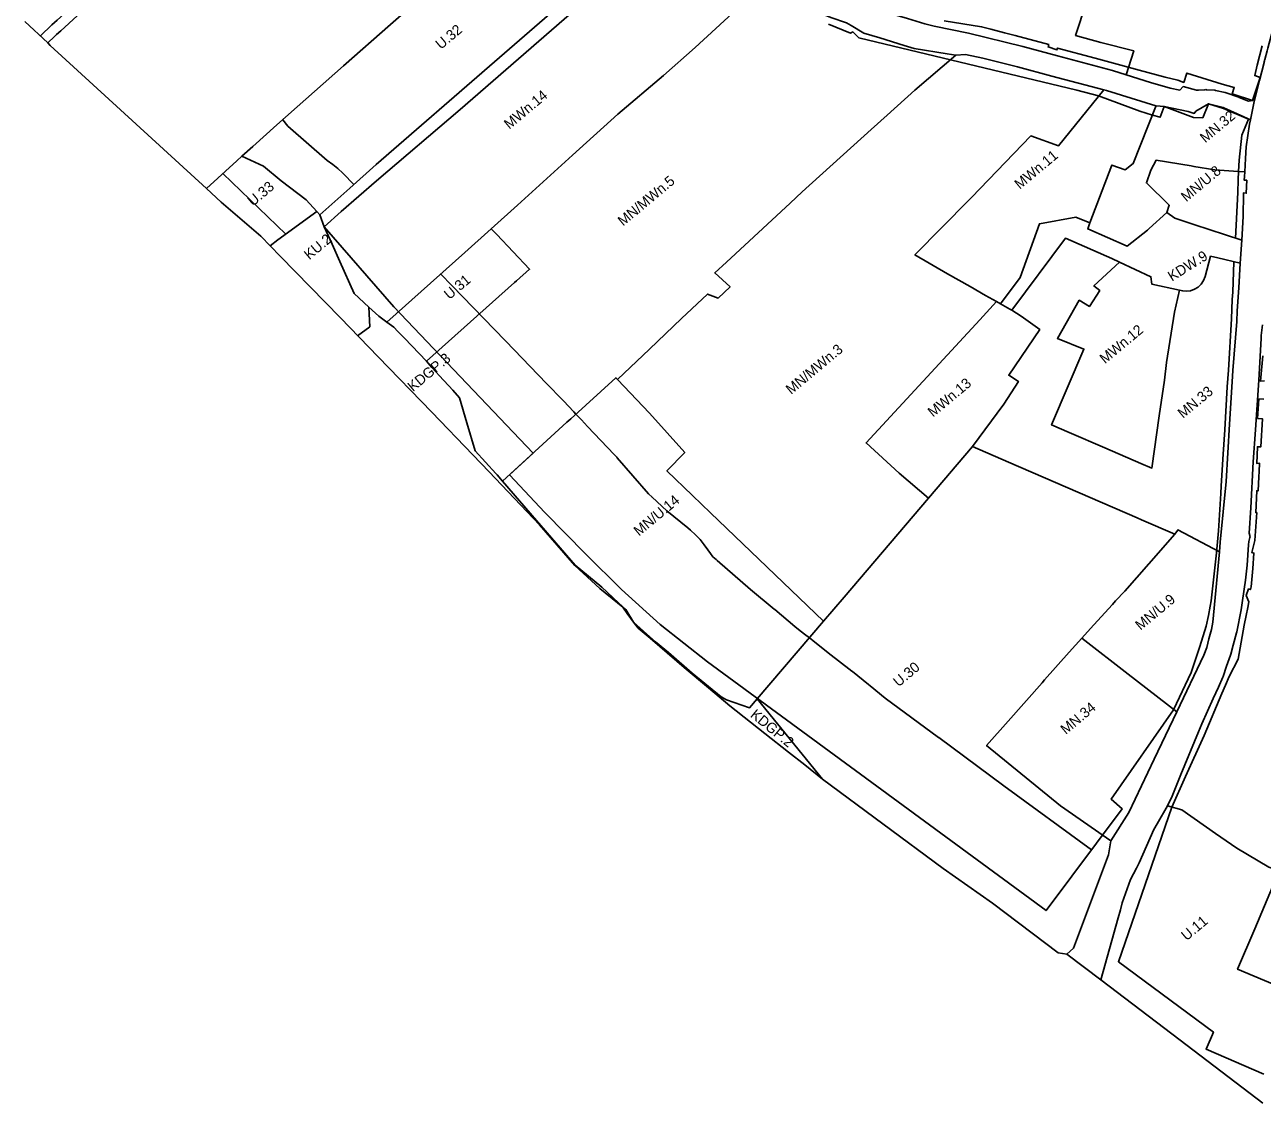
# Model space of a CAD drawing. Extents: x 7418616 to 7420822, y 5550745 to 5553106.
# Drawn here: x 7419438 to 7420041, y 5551094 to 5551619 of the extents above; entities that cross this region are included whole.
import ezdxf

# ---------------------------------------------------------------- set-up
doc = ezdxf.new("R2010")
doc.units = 0
for name, color, linetype in [('granica obszaru objętego planem', 7, 'Continuous'), ('granica strefy zwiększonej wysokości zabudowy', 7, 'Continuous'), ('linie rozgraniczające', 7, 'Continuous'), ('nieprzekraczalne linie zabudowy', 7, 'Continuous'), ('przeznaczenia terenów', 7, 'Continuous')]:
    doc.layers.add(name, color=color, linetype=linetype)

msp = doc.modelspace()

# ---------------------------------------------------------------- linework, layer by layer
at = {"layer": 'granica obszaru objętego planem'}
msp.add_lwpolyline([(7420041.04, 5551093.52), (7420000.75, 5551124.25), (7419962.19, 5551153.66), (7419945.54, 5551166.16), (7419941.34, 5551166.91), (7419909.33, 5551191.02), (7419885.31, 5551207.95), (7419826.5, 5551251.53), (7419817.94, 5551258.45), (7419810.05, 5551264.7), (7419798.45, 5551273.79), (7419781.42, 5551287.19), (7419771.03, 5551295.97), (7419759.16, 5551305.88), (7419742.57, 5551320.26), (7419736.76, 5551325.16), (7419734.5, 5551328.07), (7419731.34, 5551332.23), (7419729.3, 5551335.25), (7419718.06, 5551344.47), (7419705.9, 5551355.56), (7419688.74, 5551375.39), (7419664.22, 5551401.29), (7419656.17, 5551409.57), (7419636.17, 5551430.42), (7419610.04, 5551457.27), (7419591.7, 5551476.35), (7419562.41, 5551506.46), (7419552.94, 5551516.11), (7419533.63, 5551532.65), (7419526.39, 5551539.32), (7419450.23, 5551609.13), (7419449.2, 5551610.35), (7419437.9, 5551620.76)], dxfattribs=at)
at = {"layer": 'granica strefy zwiększonej wysokości zabudowy'}
for points in [[(7419563.59, 5551572.87), (7419566.06, 5551569.76), (7419585.29, 5551553.03), (7419587.95, 5551551.12), (7419590.48, 5551549.05), (7419592.86, 5551546.81), (7419593.2, 5551546.48), (7419598.1, 5551541.48), (7419598.26, 5551541.31)], [(7419640.56, 5551497.66), (7419645.97, 5551492.04), (7419672, 5551465.29), (7419672.25, 5551465.03), (7419692.14, 5551444.3), (7419700.07, 5551436.14), (7419700.49, 5551435.7), (7419705.3, 5551430.63), (7419705.35, 5551430.59), (7419706.43, 5551429.44)], [(7419706.34, 5551429.36), (7419709.16, 5551426.55), (7419712.11, 5551423.44), (7419725.06, 5551409.76), (7419726.33, 5551408.36), (7419726.55, 5551408.1), (7419741.75, 5551390.53), (7419743.54, 5551388.9), (7419743.56, 5551388.89), (7419750.79, 5551382.3), (7419761.01, 5551373.91), (7419762.27, 5551372.84), (7419764.66, 5551370.61), (7419766.89, 5551368.22), (7419768.97, 5551365.69), (7419770.73, 5551363.24), (7419771.93, 5551361.46), (7419773.14, 5551359.88), (7419774.81, 5551358.48), (7419775.32, 5551358.04), (7419791.56, 5551343.97), (7419803.07, 5551334.35), (7419803.3, 5551334.16), (7419813.04, 5551325.93), (7419814.94, 5551324.44), (7419817.87, 5551322.12), (7419820.16, 5551320.32)], [(7419820.16, 5551320.32), (7419821.84, 5551319), (7419829.32, 5551313.12), (7419840.89, 5551304.06), (7419841.1, 5551303.89), (7419848.99, 5551297.64), (7419849.76, 5551297.01), (7419857.1, 5551290.96), (7419883.07, 5551271.86), (7419883.22, 5551271.74), (7419914.97, 5551248.2), (7419957.62, 5551216.97)]]:
    msp.add_lwpolyline(points, dxfattribs=at)
at = {"layer": 'linie rozgraniczające'}
for p, q in [((7420030.8, 5551514.23), (7420030.08, 5551502.9)), ((7419913.29, 5551483.18), (7419911.35, 5551484.32)), ((7419899.62, 5551413.61), (7419878.15, 5551388.38)), ((7419827.08, 5551328.43), (7419794.8, 5551290.63)), ((7419794.8, 5551290.63), (7419826.5, 5551251.53))]:
    msp.add_line(p, q, dxfattribs=at)
for points in [[(7419449.2, 5551610.35), (7419452.46, 5551613.53), (7419453.31, 5551614.36), (7419455.41, 5551616.28), (7419477.43, 5551636.49), (7419488.09, 5551645.77), (7419515.75, 5551669.86), (7419570.49, 5551717.29), (7419589.38, 5551733.67), (7419610.42, 5551751.9), (7419613.77, 5551754.84), (7419627.2, 5551766.58)], [(7419537.25, 5551694.98), (7419524.25, 5551683.72), (7419519.48, 5551679.65), (7419513.7, 5551674.67), (7419507.7, 5551669.36), (7419503.04, 5551665.3), (7419495.61, 5551658.92), (7419488.4, 5551652.57), (7419483.64, 5551648.47), (7419474.37, 5551640.41), (7419458.68, 5551626.03), (7419453.73, 5551621.45), (7419451.05, 5551619.22), (7419445.5, 5551613.76)], [(7419700.4, 5551695.24), (7419687.42, 5551682.37), (7419674.24, 5551670.63), (7419662.03, 5551659.82), (7419633.04, 5551634.29), (7419616.09, 5551619.23), (7419593.15, 5551599.18), (7419560.75, 5551570.34), (7419548.95, 5551559.84), (7419543.61, 5551555.09)], [(7419974.49, 5551594.78), (7419976.92, 5551602.43), (7419978.21, 5551606.48), (7419962.1, 5551610.56), (7419949.9, 5551613.99), (7419954.99, 5551629.76), (7419950.26, 5551631.32), (7419949.77, 5551631.48), (7419940.41, 5551634.57), (7419942.5, 5551636.57), (7419948.98, 5551642.71), (7419959.79, 5551652.81), (7419962.71, 5551655.57), (7419975.98, 5551642.42), (7419989.51, 5551658.28), (7419990.82, 5551664.22), (7419994.68, 5551680.44)], [(7419753.76, 5551670.21), (7419765.49, 5551663.66), (7419774.08, 5551658.33), (7419781.54, 5551654.6), (7419788.27, 5551651.59), (7419797.81, 5551647.54), (7419808.59, 5551642.92), (7419818.54, 5551638.49), (7419827.18, 5551635.06), (7419834.06, 5551632.36), (7419844.69, 5551628.77), (7419851.67, 5551626.9), (7419867.92, 5551622.27), (7419876.46, 5551619.65), (7419881.01, 5551618.52), (7419897.68, 5551615.16), (7419924.17, 5551608.56), (7419941, 5551604.01), (7419967.8, 5551596.87), (7419974.49, 5551594.78)], [(7419744.92, 5551663.54), (7419740.88, 5551658.92), (7419736.08, 5551653.72), (7419716.86, 5551635.99), (7419650.11, 5551577.84), (7419609.28, 5551543.07), (7419592.03, 5551528.18), (7419583.75, 5551520.75)], [(7420037.19, 5551583.05), (7420039.4, 5551591.99), (7420041.71, 5551600.73), (7420041.78, 5551601.13), (7420041.87, 5551601.52), (7420041.98, 5551601.9), (7420042.12, 5551602.25), (7420043.24, 5551606.48), (7420043.61, 5551607.69), (7420047.77, 5551623.56), (7420050.61, 5551635.2), (7420052.75, 5551644.09), (7420055.5, 5551654.67)], [(7419665.14, 5551519.73), (7419677.92, 5551531.25), (7419704.78, 5551555.54), (7419726.91, 5551575.57), (7419749.02, 5551594.5), (7419764.54, 5551608.16), (7419788.65, 5551630.4), (7419794.9, 5551636.59), (7419795.65, 5551637.37)], [(7419891.54, 5551604.31), (7419887.32, 5551605), (7419871.27, 5551607.62), (7419866.3, 5551609.14), (7419854.51, 5551612.75), (7419846.73, 5551615.13), (7419840.56, 5551618.83), (7419838.33, 5551620.16), (7419830.69, 5551622.74), (7419823.43, 5551625.57), (7419814.68, 5551629.04), (7419804.46, 5551633.59), (7419795.65, 5551637.37)], [(7420041.04, 5551093.52), (7420000.75, 5551124.25), (7419962.19, 5551153.66), (7419945.54, 5551166.16), (7419941.34, 5551166.91), (7419909.33, 5551191.02), (7419885.31, 5551207.95), (7419826.5, 5551251.53), (7419817.94, 5551258.45), (7419810.05, 5551264.7), (7419798.45, 5551273.79), (7419781.42, 5551287.19), (7419771.03, 5551295.97), (7419759.16, 5551305.88), (7419742.57, 5551320.26), (7419736.76, 5551325.16), (7419734.5, 5551328.07), (7419731.34, 5551332.23), (7419729.3, 5551335.25), (7419718.06, 5551344.47), (7419705.9, 5551355.56), (7419688.74, 5551375.39), (7419664.22, 5551401.29), (7419656.17, 5551409.57), (7419636.17, 5551430.42), (7419610.04, 5551457.27), (7419591.7, 5551476.35), (7419562.41, 5551506.46), (7419552.94, 5551516.11), (7419533.63, 5551532.65), (7419526.39, 5551539.32), (7419450.23, 5551609.13), (7419449.2, 5551610.35), (7419437.9, 5551620.76)], [(7419891.54, 5551604.31), (7419871.56, 5551587.36), (7419858.1, 5551575.19), (7419850.32, 5551568.16), (7419816.68, 5551537.77), (7419810.74, 5551532.25), (7419779.73, 5551503.44), (7419774.1, 5551498.22), (7419781.52, 5551491.47), (7419775.7, 5551485.95), (7419770.54, 5551487.95), (7419757.86, 5551475.93), (7419742.26, 5551461.14), (7419726.68, 5551446.36)], [(7419963.64, 5551587.42), (7419938.36, 5551594.16), (7419921.55, 5551598.7), (7419904.75, 5551602.89), (7419896.27, 5551604.68), (7419891.54, 5551604.31)], [(7419974.49, 5551594.78), (7419986.36, 5551591.09), (7419995.89, 5551588.22), (7420000.65, 5551587.36), (7420002.35, 5551589.03), (7420008.83, 5551587.24), (7420009.81, 5551587.26), (7420012.82, 5551587.53), (7420013.28, 5551587.55), (7420013.66, 5551587.54), (7420017.78, 5551587.22), (7420018.11, 5551587.17), (7420022.72, 5551586.13), (7420023.23, 5551585.98), (7420029.44, 5551583.81), (7420029.6, 5551583.73), (7420034.08, 5551581.98), (7420035.99, 5551582.27), (7420037.19, 5551583.05)], [(7419911.35, 5551484.32), (7419906.02, 5551487.18), (7419898.57, 5551491.58), (7419887.5, 5551497.83), (7419871.61, 5551507.01), (7419897.99, 5551533.82), (7419899.1, 5551534.96), (7419928.02, 5551565.01), (7419941.53, 5551560.13), (7419963.64, 5551587.42)], [(7419963.64, 5551587.42), (7419964.87, 5551587.09), (7419988.95, 5551579.65), (7419989.01, 5551579.67), (7419989.07, 5551579.66)], [(7420035.01, 5551572.77), (7420036.67, 5551580.96), (7420037.19, 5551583.05)], [(7419956.88, 5551522.57), (7419967.46, 5551550.77), (7419974.07, 5551548.39), (7419977.89, 5551551.49), (7419988.76, 5551579.03), (7419989.07, 5551579.66)], [(7419989.07, 5551579.66), (7419993.05, 5551579.35), (7420004.64, 5551576.86), (7420007.71, 5551575.96), (7420008.47, 5551577.05), (7420014.62, 5551580.58), (7420021.79, 5551578.88), (7420022.03, 5551578.77), (7420035.01, 5551572.77)], [(7420035.01, 5551572.77), (7420034.62, 5551570.77), (7420033.03, 5551559.64), (7420032.57, 5551553.96), (7420032.25, 5551547.44)], [(7419543.61, 5551555.09), (7419541.16, 5551552.85), (7419526.39, 5551539.32)], [(7419543.61, 5551555.09), (7419554.15, 5551550.3), (7419562.9, 5551543.19), (7419574.99, 5551533.89), (7419580.25, 5551528.15)], [(7420032.25, 5551547.44), (7420029.13, 5551547.64), (7420017.77, 5551548.39), (7420007.5, 5551550.17), (7420006.25, 5551550.38), (7419989.14, 5551553.22), (7419986.59, 5551548.29), (7419984.41, 5551542.08), (7419995.5, 5551531.18), (7419994.26, 5551527.7)], [(7420032.25, 5551547.44), (7420032.14, 5551545.15), (7420032.03, 5551543.43), (7420033.27, 5551543.39), (7420033.04, 5551537.07), (7420031.62, 5551537.23), (7420031.6, 5551536.82), (7420031.5, 5551525.65), (7420030.8, 5551514.23)], [(7419557.49, 5551511.48), (7419561.28, 5551514.28), (7419580.15, 5551528.14), (7419580.25, 5551528.15)], [(7419580.25, 5551528.15), (7419581.63, 5551526.48), (7419583.75, 5551520.75)], [(7419956.88, 5551522.57), (7419949.98, 5551525.32), (7419932.27, 5551522.17), (7419922.79, 5551495.95), (7419913.29, 5551483.18)], [(7419994.26, 5551527.7), (7419985.66, 5551519.84), (7419984.83, 5551519.03), (7419975.04, 5551511.25), (7419955.79, 5551519.67), (7419956.88, 5551522.57)], [(7420030.8, 5551514.23), (7420014.99, 5551519.42), (7420008.04, 5551521.7), (7419998.17, 5551524.94), (7419994.26, 5551527.7)], [(7419583.75, 5551520.75), (7419587.6, 5551512.2), (7419591.4, 5551503.76), (7419598.4, 5551488.19), (7419605.57, 5551481.59)], [(7419614.34, 5551474.22), (7419652.33, 5551508.19), (7419665.14, 5551519.73)], [(7419665.14, 5551519.73), (7419667.89, 5551516.92), (7419683.86, 5551500.05), (7419677.52, 5551494.45), (7419676.54, 5551493.59), (7419633.62, 5551455.16)], [(7419971.32, 5551503.53), (7419967.51, 5551505.27), (7419944.92, 5551515.16), (7419918.75, 5551480.01)], [(7420030.08, 5551502.9), (7420019.09, 5551505.51), (7420015.61, 5551506.33), (7420013, 5551496.5), (7420012.25, 5551494.56), (7420011.1, 5551492.82), (7420009.6, 5551491.36), (7420007.84, 5551490.26), (7420005.86, 5551489.57), (7420003.8, 5551489.3), (7420002.1, 5551489.43), (7420000.44, 5551489.84)], [(7420000.44, 5551489.84), (7419998.04, 5551479.15), (7419994.13, 5551454.49), (7419993.26, 5551445.88), (7419990.54, 5551428.61), (7419987.04, 5551403.08), (7419981.62, 5551405.41), (7419964.14, 5551412.95), (7419946.66, 5551420.47), (7419938.17, 5551424.13), (7419953.96, 5551461.13), (7419941.05, 5551466.28), (7419951.69, 5551484.9), (7419956.59, 5551481.89), (7419961.64, 5551489.6), (7419958.83, 5551491.92), (7419971.32, 5551503.53)], [(7419971.32, 5551503.53), (7419986.56, 5551496.37), (7419987.04, 5551492.74), (7420000.44, 5551489.84)], [(7420030.08, 5551502.9), (7420029.39, 5551490.89), (7420028.64, 5551479.75), (7420028.43, 5551474.6), (7420026.5, 5551450.65), (7420026.16, 5551445.16), (7420024.91, 5551424.59), (7420023.25, 5551396.59), (7420020.37, 5551366.95), (7420019.92, 5551362.28)], [(7419600.09, 5551467.62), (7419605.96, 5551472.01), (7419605.57, 5551481.59)], [(7419605.57, 5551481.59), (7419610.34, 5551477.21), (7419614.34, 5551474.22)], [(7419878.15, 5551388.38), (7419863.85, 5551400.66), (7419847.77, 5551415.34), (7419903.27, 5551475.3), (7419911.35, 5551484.32)], [(7419913.29, 5551483.18), (7419917.78, 5551480.53), (7419918.75, 5551480.01)], [(7419918.75, 5551480.01), (7419923.36, 5551477.09), (7419932.41, 5551470.63), (7419917.33, 5551448.35), (7419922.05, 5551445.34), (7419914.87, 5551434.25), (7419899.62, 5551413.61)], [(7419614.34, 5551474.22), (7419617.64, 5551471.84), (7419619.73, 5551469.69), (7419622.96, 5551466.38), (7419633.62, 5551455.16)], [(7419994.65, 5551238.46), (7419996.9, 5551243.19), (7420001.22, 5551253.76), (7420009.71, 5551274.53), (7420011.35, 5551278.4), (7420016.9, 5551290.81), (7420019.43, 5551296.29), (7420021.64, 5551301.17), (7420021.8, 5551301.58), (7420023.44, 5551306.53), (7420025.36, 5551311.95), (7420025.5, 5551312.4), (7420026.56, 5551316.74), (7420028.32, 5551322.74), (7420028.45, 5551323.27), (7420030.47, 5551334.01), (7420031.26, 5551338.64), (7420032.64, 5551348.53), (7420033.5, 5551355.81), (7420034.16, 5551365.65), (7420034.25, 5551367.29), (7420034.75, 5551369.21), (7420034.86, 5551369.62), (7420034.49, 5551371.37), (7420035.22, 5551383.79), (7420036.38, 5551406.22), (7420037.44, 5551421.72), (7420039.14, 5551446.03), (7420040.31, 5551466.34), (7420040.36, 5551467.76), (7420040.89, 5551472.88)], [(7419633.62, 5551455.16), (7419636.3, 5551452.2), (7419641.94, 5551445.96), (7419644.46, 5551443.17), (7419646.4, 5551441.02), (7419649.76, 5551437.31), (7419653.33, 5551425.21), (7419657.34, 5551411.58), (7419667.43, 5551400.52), (7419668.1, 5551399.78), (7419670.73, 5551396.74)], [(7419670.73, 5551396.74), (7419702.03, 5551425.44), (7419703.91, 5551427.15), (7419725.89, 5551447.17), (7419726.68, 5551446.36)], [(7419726.68, 5551446.36), (7419742.27, 5551429.88), (7419759.49, 5551410.68), (7419750.74, 5551401.7), (7419763.28, 5551389.66), (7419771.97, 5551381.32), (7419827.08, 5551328.43)], [(7419998.18, 5551370.87), (7419981.9, 5551377.92), (7419979.83, 5551378.82), (7419917.14, 5551406.02), (7419899.62, 5551413.61)], [(7419670.73, 5551396.74), (7419687.25, 5551377.63), (7419706.08, 5551355.86), (7419719.09, 5551345), (7419727.24, 5551337.46), (7419730.77, 5551334.2), (7419734.5, 5551328.07)], [(7419878.15, 5551388.38), (7419837.12, 5551340.18), (7419827.08, 5551328.43)], [(7419998.18, 5551370.87), (7419999.49, 5551372.75), (7419999.75, 5551373.07), (7420019.92, 5551362.28)], [(7419952.85, 5551320.2), (7419957.15, 5551324.96), (7419967.7, 5551336.46), (7419967.88, 5551336.65), (7419969.36, 5551338.34), (7419973.8, 5551343.15), (7419985.54, 5551356.36), (7419998.18, 5551370.87)], [(7420019.92, 5551362.28), (7420016.69, 5551328.05), (7420016.12, 5551324.45), (7420014.77, 5551319.9), (7420013.75, 5551315.72), (7420012.39, 5551311.87), (7419999.26, 5551284.26)], [(7419734.5, 5551328.07), (7419739.33, 5551323.55), (7419745.14, 5551318.37), (7419751.52, 5551313.18), (7419763.12, 5551303.09), (7419777.24, 5551291.59), (7419779.87, 5551290.09), (7419790.92, 5551286.25), (7419794.8, 5551290.63)], [(7419967.1, 5551221.46), (7419942.55, 5551238.52), (7419906.51, 5551267.87), (7419917.01, 5551279.8), (7419933.54, 5551298.51), (7419934.76, 5551299.88), (7419946.74, 5551313.43), (7419952.85, 5551320.2)], [(7419952.85, 5551320.2), (7419975.55, 5551302.62), (7419999.26, 5551284.26)], [(7419999.26, 5551284.26), (7419988.21, 5551261.17), (7419975.79, 5551235.23), (7419967.1, 5551221.46)], [(7419962.19, 5551153.66), (7419970.63, 5551183.94), (7419971.7, 5551187.8), (7419972.6, 5551191.27), (7419976.67, 5551202.61), (7419979.58, 5551208.06), (7419980.89, 5551210.72), (7419988.05, 5551227), (7419989.55, 5551229.71), (7419994.65, 5551238.46)], [(7419994.65, 5551238.46), (7420001.56, 5551236.47), (7420018.02, 5551224.98), (7420028.47, 5551217.79), (7420043.94, 5551208.61), (7420049.1, 5551206.8), (7420047.93, 5551204.04), (7420037.16, 5551178.61), (7420028.79, 5551158.84), (7420063.17, 5551144.43), (7420064.18, 5551147.79), (7420103.62, 5551135.67)], [(7419945.54, 5551166.16), (7419948.86, 5551169.16), (7419965.98, 5551214.61), (7419967.1, 5551221.46)]]:
    msp.add_lwpolyline(points, dxfattribs=at)
at = {"layer": 'nieprzekraczalne linie zabudowy'}
for points in [[(7419581.63, 5551526.48), (7419596.27, 5551539.53), (7419609.17, 5551550.99), (7419666.82, 5551601.15), (7419717.93, 5551645.65), (7419724.41, 5551651.75), (7419730.6, 5551657.61), (7419731.91, 5551658.88), (7419735.61, 5551663.08), (7419736.33, 5551663.88), (7419736.76, 5551664.29), (7419721.88, 5551673.44), (7419717.65, 5551676.06), (7419713.06, 5551679.54), (7419709.33, 5551682.67), (7419701.95, 5551689.05), (7419697.91, 5551692.77)], [(7419829.56, 5551619.42), (7419840.14, 5551615.11), (7419841.28, 5551615.71), (7419844.23, 5551612.82), (7419950.48, 5551587.3), (7419960.99, 5551584.51), (7419981.14, 5551577.1), (7419987.32, 5551575.15), (7419991.15, 5551574.11), (7419993.05, 5551579.35), (7420007.25, 5551574.02), (7420011.79, 5551573.85), (7420014.62, 5551580.58), (7420021.89, 5551578.41), (7420034.13, 5551573.17), (7420030.83, 5551565.38), (7420029.63, 5551553.12), (7420029.18, 5551547.59), (7420029.07, 5551543.56), (7420028.95, 5551537.44), (7420027.82, 5551515.21)], [(7419885.86, 5551621.13), (7419904.04, 5551618.18), (7419908.64, 5551616.96), (7419915.21, 5551615.32), (7419920.4, 5551613.96), (7419936.79, 5551609.57), (7419936.48, 5551608.39), (7419940.81, 5551606.94), (7419941.05, 5551607.81), (7419959.48, 5551602.96), (7419980.87, 5551597.12), (7419993.46, 5551593.65), (7419999.61, 5551592.18), (7420002.56, 5551591.06), (7420004, 5551595.59), (7420021.3, 5551590.16), (7420027.13, 5551588.52), (7420026.15, 5551585.48), (7420035.99, 5551582.27), (7420039.8, 5551593.51), (7420037.14, 5551594.39), (7420038.39, 5551599.48), (7420040.84, 5551608.88)], [(7419534.36, 5551546.62), (7419565.12, 5551517.1)], [(7419583.75, 5551520.75), (7419617.71, 5551481.68), (7419685.68, 5551410.45), (7419674.06, 5551399.79), (7419691.27, 5551381.46), (7419711.24, 5551361.15), (7419728.58, 5551343.98), (7419747.42, 5551326.88), (7419770.56, 5551308.72), (7419935.52, 5551187.42), (7419972.6, 5551237.02), (7419967.27, 5551241.69), (7419997.56, 5551285.33), (7420006.18, 5551303.55), (7420010.31, 5551315.63), (7420010.43, 5551316.12), (7420013.42, 5551326.09), (7420014.6, 5551331.18), (7420015.46, 5551335.84), (7420015.97, 5551338.46), (7420018.59, 5551361.85), (7420019.43, 5551372.5), (7420020.55, 5551390.75), (7420020.72, 5551394.45), (7420021.69, 5551409.89), (7420022.64, 5551421.69), (7420023.76, 5551442.66), (7420024.36, 5551450.76), (7420025.78, 5551475.92), (7420026.21, 5551485.24), (7420026.41, 5551488.92), (7420026.98, 5551503.63)], [(7420041.95, 5551445.68), (7420039.91, 5551445.49), (7420041.03, 5551457.85)], [(7420041.53, 5551107.62), (7420013.42, 5551119.86), (7420017.04, 5551128.24), (7419970.75, 5551162.51), (7419996.82, 5551237.84), (7420003.39, 5551252.74), (7420012.49, 5551272.74), (7420021.15, 5551293.28), (7420022.95, 5551297.24), (7420024.61, 5551301.52), (7420029.13, 5551309.89), (7420031.99, 5551326.58), (7420033.02, 5551331.3), (7420033.81, 5551335.14), (7420034.26, 5551337.98), (7420032.9, 5551340.93), (7420034.18, 5551344.19), (7420035.07, 5551343.87), (7420035.47, 5551345.3), (7420036.22, 5551354.17), (7420036.72, 5551361.64), (7420035.76, 5551361.94), (7420037.22, 5551367.73), (7420038.17, 5551381.43), (7420037.68, 5551381.45), (7420038.09, 5551392.03), (7420038.81, 5551391.97), (7420039.15, 5551398.92), (7420039.24, 5551401.51), (7420039.55, 5551405.42), (7420038.1, 5551405.41), (7420038.47, 5551413.5), (7420040.13, 5551413.47), (7420040.96, 5551427.09), (7420038.51, 5551427.3), (7420039.2, 5551436.8), (7420041.55, 5551436.77)]]:
    msp.add_lwpolyline(points, dxfattribs=at)

# ---------------------------------------------------------------- texts
at = {"layer": 'przeznaczenia terenów'}
for s, rotation, p in [('U.32', 39.84394, (7419640.63, 5551606.91)), ('MWn.14', 39.84394, (7419673.98, 5551568.02)), ('MN.32', 39.84394, (7420013.04, 5551561.37)), ('MWn.11', 39.84394, (7419922.68, 5551538.75)), ('MN/U.8', 39.84394, (7420003.79, 5551532.63)), ('U.33', 39.84394, (7419549.04, 5551530.48)), ('MN/MWn.5', 39.84394, (7419729.41, 5551520.82)), ('KU.2', 39.84394, (7419576.54, 5551504.37)), ('KDW.9', 32.15831, (7419996.82, 5551493.91)), ('U.31', 39.84394, (7419644.79, 5551484.98)), ('MWn.12', 39.84394, (7419964.19, 5551453.7)), ('MN/MWn.3', 39.84394, (7419811.28, 5551438.74)), ('KDGP.3', 39.84394, (7419627.05, 5551440.08)), ('MWn.13', 39.84394, (7419880.43, 5551427.68)), ('MN.33', 39.84394, (7420002.2, 5551427.07)), ('MN/U.14', 39.84394, (7419737.15, 5551369.72)), ('MN/U.9', 39.84394, (7419981.53, 5551323.79)), ('U.30', 39.84394, (7419863.59, 5551296.2)), ('MN.34', 39.84394, (7419945.1, 5551273.04)), ('KDGP.2', 320.62214, (7419791.04, 5551282.16)), ('U.11', 39.84394, (7420003.93, 5551172.48))]:
    msp.add_text(s, height=5, rotation=rotation, dxfattribs=at).set_placement(p)

doc.saveas('drawing.dxf')
